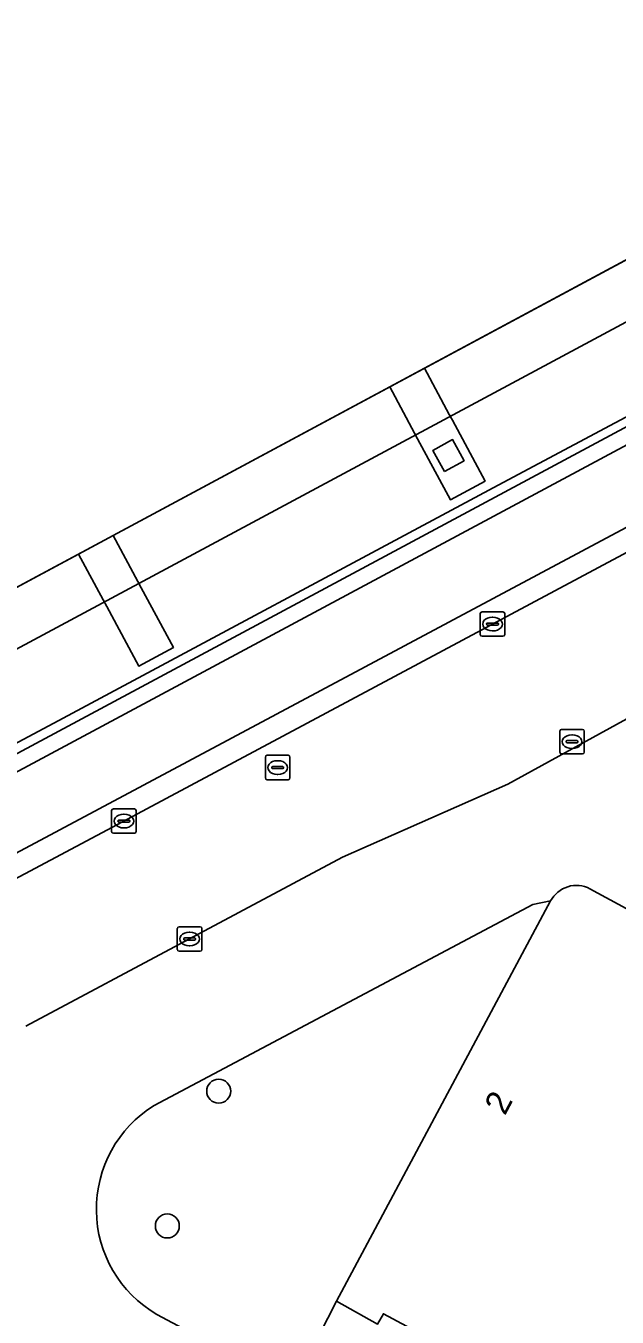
# Model space of a CAD drawing. Extents: x 159489 to 160304, y 383825 to 384531.
# Drawn here: x 159576.6 to 159600.7, y 384336.8 to 384389.5 of the extents above; entities that cross this region are included whole.
import ezdxf

# ---------------------------------------------------------------- set-up
doc = ezdxf.new("R2010")
doc.units = 0
for name, color, linetype in [('IMGEO_Berm_open', 7, 'Continuous'), ('IMGEO_Boom', 7, 'Continuous'), ('IMGEO_Dek', 7, 'Continuous'), ('IMGEO_Fietspad_gesloten', 7, 'Continuous'), ('IMGEO_Groenvoorziening', 7, 'Continuous'), ('IMGEO_Kolk', 7, 'Continuous'), ('IMGEO_Pand', 7, 'Continuous'), ('IMGEO_Pand_nummerreeks', 7, 'Continuous'), ('IMGEO_Pijler', 7, 'Continuous'), ('IMGEO_Rijbaan_lokaal_gesloten', 7, 'Continuous'), ('IMGEO_Rijbaan_regionaal_gesloten', 7, 'Continuous'), ('IMGEO_Rioolput', 7, 'Continuous'), ('IMGEO_Verkeerseiland_open', 7, 'Continuous'), ('IMGEO_Voetpad_open', 7, 'Continuous')]:
    doc.layers.add(name, color=color, linetype=linetype)

msp = doc.modelspace()

# ---------------------------------------------------------------- linework, layer by layer
at = {"layer": 'IMGEO_Berm_open'}
msp.add_lwpolyline([(159506.853, 384322.564), (159549.818, 384345.616), (159555.628, 384348.734), (159555.907, 384348.884), (159569.121, 384355.973), (159618.393, 384382.41), (159620.115, 384383.333), (159619.966, 384383.61), (159617.94, 384382.518), (159616.597, 384381.793), (159595.84, 384370.739), (159577.717, 384361.023), (159568.472, 384356.103), (159557.818, 384350.431), (159555.814, 384349.365), (159555.254, 384349.067), (159549.006, 384345.74), (159548.566, 384345.506), (159543.661, 384342.895), (159543.262, 384342.679), (159524.772, 384332.69)], dxfattribs=at)
at = {"layer": 'IMGEO_Boom'}
for centre in [(159584.446, 384346.009), (159582.351, 384340.508)]:
    msp.add_circle(centre, 0.489, dxfattribs=at)
at = {"layer": 'IMGEO_Dek'}
msp.add_lwpolyline([(159488.508, 384319.441), (159491.36, 384314.274), (159493.126, 384315.218), (159493.745, 384315.549), (159500.607, 384319.217), (159503.5, 384320.764), (159504.356, 384321.224), (159506.58, 384322.417), (159506.853, 384322.564), (159543.492, 384342.222), (159549.818, 384345.616), (159555.628, 384348.734), (159555.907, 384348.884), (159569.121, 384355.973), (159618.393, 384382.41), (159620.115, 384383.333), (159619.966, 384383.61), (159618.385, 384386.561), (159617.271, 384388.641)], close=True, dxfattribs=at)
at = {"layer": 'IMGEO_Fietspad_gesloten'}
for points in [[(159700.906, 384425.794), (159682.221, 384415.781), (159622.046, 384383.628), (159620.424, 384382.758), (159619.93, 384382.493), (159571.207, 384356.355), (159556.599, 384348.661)], [(159562.194, 384348.219), (159572.535, 384353.778), (159693.459, 384418.367)]]:
    msp.add_lwpolyline(points, dxfattribs=at)
at = {"layer": 'IMGEO_Groenvoorziening'}
for points in [[(159597.986, 384353.77), (159597.261, 384353.625), (159581.812, 384345.424)], [(159581.925, 384336.895), (159587.468, 384333.95), (159589.25, 384337.446), (159597.986, 384353.77)]]:
    msp.add_lwpolyline(points, dxfattribs=at)
msp.add_arc((159584.432, 384341.193), 4.976, 121.7686, 239.7495, dxfattribs=at)
at = {"layer": 'IMGEO_Kolk'}
for p, q in [((159595.114, 384364.644), (159595.114, 384365.496)), ((159595.189, 384365.57), (159596.041, 384365.57)), ((159595.602, 384365.35), (159595.627, 384365.35)), ((159596.115, 384365.496), (159596.115, 384364.644)), ((159595.373, 384365.064), (159595.373, 384365.076)), ((159595.811, 384365.027), (159595.413, 384365.027)), ((159595.416, 384365.113), (159595.814, 384365.113)), ((159595.625, 384364.79), (159595.6, 384364.79)), ((159595.857, 384365.076), (159595.857, 384365.064)), ((159596.041, 384364.57), (159595.189, 384364.57)), ((159598.358, 384359.845), (159598.358, 384360.697)), ((159598.433, 384360.771), (159599.285, 384360.771)), ((159598.846, 384360.551), (159598.871, 384360.551)), ((159599.359, 384360.697), (159599.359, 384359.845)), ((159598.617, 384360.265), (159598.617, 384360.277)), ((159599.055, 384360.228), (159598.657, 384360.228)), ((159598.66, 384360.314), (159599.058, 384360.314)), ((159598.869, 384359.991), (159598.844, 384359.991)), ((159599.101, 384360.277), (159599.101, 384360.265)), ((159599.285, 384359.771), (159598.433, 384359.771)), ((159580.08, 384356.605), (159580.08, 384357.457)), ((159580.155, 384357.531), (159581.007, 384357.531)), ((159580.568, 384357.311), (159580.593, 384357.311)), ((159581.081, 384357.457), (159581.081, 384356.605)), ((159580.339, 384357.025), (159580.339, 384357.037)), ((159580.777, 384356.988), (159580.379, 384356.988)), ((159580.382, 384357.074), (159580.78, 384357.074)), ((159580.823, 384357.037), (159580.823, 384357.025)), ((159581.007, 384356.531), (159580.155, 384356.531)), ((159580.591, 384356.751), (159580.566, 384356.751)), ((159582.759, 384351.794), (159582.759, 384352.646)), ((159582.834, 384352.72), (159583.686, 384352.72)), ((159583.76, 384352.646), (159583.76, 384351.794)), ((159583.018, 384352.214), (159583.018, 384352.226)), ((159583.456, 384352.177), (159583.058, 384352.177)), ((159583.061, 384352.263), (159583.459, 384352.263)), ((159583.247, 384352.5), (159583.272, 384352.5)), ((159583.502, 384352.226), (159583.502, 384352.214)), ((159583.686, 384351.72), (159582.834, 384351.72)), ((159583.27, 384351.94), (159583.245, 384351.94))]:
    msp.add_line(p, q, dxfattribs=at)
for points in [[(159595.114, 384364.644), (159595.114, 384365.496)], [(159595.189, 384365.57), (159596.041, 384365.57)], [(159596.115, 384365.496), (159596.115, 384364.644)], [(159596.041, 384364.57), (159595.189, 384364.57)], [(159598.358, 384359.845), (159598.358, 384360.697)], [(159598.433, 384360.771), (159599.285, 384360.771)], [(159599.359, 384360.697), (159599.359, 384359.845)], [(159599.285, 384359.771), (159598.433, 384359.771)], [(159580.08, 384356.605), (159580.08, 384357.457)], [(159580.155, 384357.531), (159581.007, 384357.531)], [(159581.081, 384357.457), (159581.081, 384356.605)], [(159581.007, 384356.531), (159580.155, 384356.531)], [(159582.759, 384351.794), (159582.759, 384352.646)], [(159582.834, 384352.72), (159583.686, 384352.72)], [(159583.76, 384352.646), (159583.76, 384351.794)], [(159583.686, 384351.72), (159582.834, 384351.72)]]:
    msp.add_lwpolyline(points, dxfattribs=at)
for centre, radius, start, end in [((159595.191, 384365.494), 0.0765, 91.552, 178.448), ((159595.191, 384365.494), 0.0765, 91.552, 178.448), ((159596.039, 384365.494), 0.0765, 1.552, 88.448), ((159596.039, 384365.494), 0.0765, 1.552, 88.448), ((159595.413, 384365.073), 0.0403, 85.8775, 175.7526), ((159595.41, 384365.063), 0.0366, 178.938, 274.7102), ((159595.814, 384365.07), 0.043, 264.8664, 352.4533), ((159595.818, 384365.075), 0.0386, 1.7309, 96.639), ((159595.191, 384364.646), 0.0765, 181.552, 268.448), ((159595.191, 384364.646), 0.0765, 181.552, 268.448), ((159596.039, 384364.646), 0.0765, 271.552, 358.448), ((159596.039, 384364.646), 0.0765, 271.552, 358.448), ((159598.435, 384360.695), 0.0765, 91.552, 178.448), ((159598.435, 384360.695), 0.0765, 91.552, 178.448), ((159599.283, 384360.695), 0.0765, 1.552, 88.448), ((159599.283, 384360.695), 0.0765, 1.552, 88.448), ((159598.657, 384360.274), 0.0403, 85.8775, 175.7526), ((159598.654, 384360.264), 0.0366, 178.938, 274.7102), ((159599.058, 384360.271), 0.043, 264.8664, 352.4533), ((159599.062, 384360.276), 0.0386, 1.7309, 96.639), ((159598.435, 384359.847), 0.0765, 181.552, 268.448), ((159598.435, 384359.847), 0.0765, 181.552, 268.448), ((159599.283, 384359.847), 0.0765, 271.552, 358.448), ((159599.283, 384359.847), 0.0765, 271.552, 358.448), ((159580.157, 384357.455), 0.0765, 91.552, 178.448), ((159580.157, 384357.455), 0.0765, 91.552, 178.448), ((159581.005, 384357.455), 0.0765, 1.552, 88.448), ((159581.005, 384357.455), 0.0765, 1.552, 88.448), ((159580.379, 384357.034), 0.0403, 85.8775, 175.7526), ((159580.376, 384357.024), 0.0366, 178.938, 274.7102), ((159580.78, 384357.031), 0.043, 264.8664, 352.4533), ((159580.784, 384357.036), 0.0386, 1.7309, 96.639), ((159580.157, 384356.607), 0.0765, 181.552, 268.448), ((159580.157, 384356.607), 0.0765, 181.552, 268.448), ((159581.005, 384356.607), 0.0765, 271.552, 358.448), ((159581.005, 384356.607), 0.0765, 271.552, 358.448), ((159582.836, 384352.644), 0.0765, 91.552, 178.448), ((159582.836, 384352.644), 0.0765, 91.552, 178.448), ((159583.684, 384352.644), 0.0765, 1.552, 88.448), ((159583.684, 384352.644), 0.0765, 1.552, 88.448), ((159583.058, 384352.223), 0.0403, 85.8775, 175.7526), ((159583.055, 384352.213), 0.0366, 178.938, 274.7102), ((159583.459, 384352.22), 0.043, 264.8664, 352.4533), ((159583.463, 384352.225), 0.0386, 1.7309, 96.639), ((159582.836, 384351.796), 0.0765, 181.552, 268.448), ((159582.836, 384351.796), 0.0765, 181.552, 268.448), ((159583.684, 384351.796), 0.0765, 271.552, 358.448), ((159583.684, 384351.796), 0.0765, 271.552, 358.448)]:
    msp.add_arc(centre, radius, start, end, dxfattribs=at)
for centre, major_axis, ratio, start_param, end_param in [((159595.601, 384365.07), (-0.387, 0.002), 0.722429, 4.712389, 7.853982), ((159595.626, 384365.07), (-0.39, 0.002), 0.717154, 1.570796, 4.712389), ((159598.845, 384360.271), (-0.387, 0.002), 0.722429, 4.712389, 7.853982), ((159598.87, 384360.271), (-0.39, 0.002), 0.717154, 1.570796, 4.712389), ((159580.567, 384357.031), (-0.387, 0.002), 0.722429, 4.712389, 7.853982), ((159580.592, 384357.031), (-0.39, 0.002), 0.717154, 1.570796, 4.712389), ((159583.246, 384352.22), (-0.387, 0.002), 0.722429, 4.712389, 7.853982), ((159583.271, 384352.22), (-0.39, 0.002), 0.717154, 1.570796, 4.712389)]:
    msp.add_ellipse(centre, major_axis=major_axis, ratio=ratio, start_param=start_param, end_param=end_param, dxfattribs=at)
at = {"layer": 'IMGEO_Pand'}
for points in [[(159682.896, 384327.942), (159623.816, 384359.804), (159624.059, 384360.245), (159623.309, 384360.657), (159623.062, 384360.208), (159618.493, 384362.659), (159618.727, 384363.096), (159617.547, 384363.691), (159617.084, 384363.924), (159612.282, 384355.014), (159609.456, 384356.538), (159609.794, 384357.17), (159609.409, 384357.376), (159608.96, 384356.518), (159606.901, 384357.605), (159605.205, 384354.438), (159602.39, 384355.944), (159601.071, 384353.466), (159599.589, 384354.271)], [(159597.986, 384353.77), (159589.25, 384337.446), (159590.921, 384336.498), (159591.162, 384336.929), (159595.684, 384334.503)]]:
    msp.add_lwpolyline(points, dxfattribs=at)
msp.add_arc((159599.038, 384353.22), 1.187, 62.3087, 152.4035, dxfattribs=at)
at = {"layer": 'IMGEO_Pijler'}
for points in [[(159592.84, 384375.511), (159591.422, 384374.749), (159592.433, 384372.865), (159592.56, 384372.628), (159593.894, 384370.142), (159595.312, 384370.903), (159593.976, 384373.392), (159593.851, 384373.625)], [(159593.661, 384371.296), (159594.458, 384371.735), (159593.983, 384372.597), (159593.186, 384372.158)], [(159593.661, 384371.296), (159593.186, 384372.158), (159593.983, 384372.597), (159594.458, 384371.735)], [(159580.139, 384368.685), (159578.728, 384367.927), (159579.736, 384366.053), (159579.879, 384365.787), (159581.186, 384363.356), (159582.596, 384364.114), (159581.288, 384366.547), (159581.147, 384366.81)]]:
    msp.add_lwpolyline(points, close=True, dxfattribs=at)
at = {"layer": 'IMGEO_Rijbaan_lokaal_gesloten'}
for points in [[(159696.183, 384418.774), (159693.863, 384417.603), (159580.529, 384357.003), (159566.867, 384349.736)], [(159576.58, 384348.662), (159583.26, 384352.22), (159589.5, 384355.56), (159596.233, 384358.541), (159604.138, 384362.877), (159611.421, 384366.774), (159627.528, 384375.393), (159633.379, 384378.441), (159633.124, 384378.917), (159634.128, 384379.44)]]:
    msp.add_lwpolyline(points, dxfattribs=at)
at = {"layer": 'IMGEO_Rijbaan_regionaal_gesloten'}
msp.add_lwpolyline([(159489.531, 384317.589), (159499.262, 384322.788), (159516.94, 384332.242), (159553.091, 384351.689), (159570.032, 384360.747), (159613.14, 384383.883), (159618.33, 384386.664), (159617.271, 384388.641), (159488.508, 384319.441)], close=True, dxfattribs=at)
msp.add_lwpolyline([(159524.772, 384332.69), (159543.262, 384342.679), (159543.661, 384342.895), (159548.566, 384345.506), (159549.006, 384345.74), (159555.254, 384349.067), (159555.814, 384349.365), (159557.818, 384350.431), (159568.472, 384356.103), (159577.717, 384361.023), (159595.84, 384370.739), (159616.597, 384381.793), (159617.94, 384382.518), (159619.966, 384383.61), (159618.33, 384386.664), (159613.14, 384383.883), (159570.032, 384360.747), (159553.091, 384351.689), (159516.94, 384332.242)], dxfattribs=at)
at = {"layer": 'IMGEO_Rioolput'}
for p, q in [((159586.352, 384358.789), (159586.352, 384359.641)), ((159586.427, 384359.715), (159587.279, 384359.715)), ((159586.84, 384359.495), (159586.865, 384359.495)), ((159587.353, 384359.641), (159587.353, 384358.789)), ((159586.611, 384359.209), (159586.611, 384359.221)), ((159587.049, 384359.172), (159586.651, 384359.172)), ((159586.654, 384359.258), (159587.052, 384359.258)), ((159586.863, 384358.935), (159586.838, 384358.935)), ((159587.095, 384359.221), (159587.095, 384359.209)), ((159587.279, 384358.715), (159586.427, 384358.715))]:
    msp.add_line(p, q, dxfattribs=at)
for points in [[(159586.352, 384358.789), (159586.352, 384359.641)], [(159586.427, 384359.715), (159587.279, 384359.715)], [(159587.353, 384359.641), (159587.353, 384358.789)], [(159587.279, 384358.715), (159586.427, 384358.715)]]:
    msp.add_lwpolyline(points, dxfattribs=at)
for centre, radius, start, end in [((159586.429, 384359.639), 0.0765, 91.552, 178.448), ((159586.429, 384359.639), 0.0765, 91.552, 178.448), ((159587.277, 384359.639), 0.0765, 1.552, 88.448), ((159587.277, 384359.639), 0.0765, 1.552, 88.448), ((159586.651, 384359.218), 0.0403, 85.8775, 175.7526), ((159586.648, 384359.208), 0.0366, 178.938, 274.7102), ((159587.052, 384359.215), 0.043, 264.8664, 352.4533), ((159587.056, 384359.22), 0.0386, 1.7309, 96.639), ((159586.429, 384358.791), 0.0765, 181.552, 268.448), ((159586.429, 384358.791), 0.0765, 181.552, 268.448), ((159587.277, 384358.791), 0.0765, 271.552, 358.448), ((159587.277, 384358.791), 0.0765, 271.552, 358.448)]:
    msp.add_arc(centre, radius, start, end, dxfattribs=at)
for centre, major_axis, ratio, start_param, end_param in [((159586.839, 384359.215), (-0.387, 0.002), 0.722429, 4.712389, 7.853982), ((159586.864, 384359.215), (-0.39, 0.002), 0.717154, 1.570796, 4.712389)]:
    msp.add_ellipse(centre, major_axis=major_axis, ratio=ratio, start_param=start_param, end_param=end_param, dxfattribs=at)
at = {"layer": 'IMGEO_Verkeerseiland_open'}
for points in [[(159693.863, 384417.603), (159693.459, 384418.367), (159572.535, 384353.778), (159562.194, 384348.219)], [(159566.867, 384349.736), (159580.529, 384357.003), (159693.863, 384417.603)]]:
    msp.add_lwpolyline(points, dxfattribs=at)
at = {"layer": 'IMGEO_Voetpad_open'}
for points in [[(159555.907, 384348.884), (159556.599, 384348.661), (159571.207, 384356.355), (159619.93, 384382.493)], [(159604.103, 384381.564), (159592.84, 384375.511), (159593.851, 384373.625), (159593.976, 384373.392), (159595.312, 384370.903), (159593.894, 384370.142), (159592.56, 384372.628), (159592.433, 384372.865), (159591.422, 384374.749), (159580.139, 384368.685), (159581.147, 384366.81), (159581.288, 384366.547), (159582.596, 384364.114), (159581.186, 384363.356), (159579.879, 384365.787), (159579.736, 384366.053), (159578.728, 384367.927), (159567.46, 384361.871)], [(159599.589, 384354.271), (159601.071, 384353.466), (159602.39, 384355.944), (159605.205, 384354.438), (159606.901, 384357.605), (159608.96, 384356.518), (159609.409, 384357.376), (159609.794, 384357.17), (159609.456, 384356.538), (159612.282, 384355.014), (159617.084, 384363.924), (159611.421, 384366.774), (159604.138, 384362.877), (159596.233, 384358.541), (159589.5, 384355.56), (159583.26, 384352.22), (159576.58, 384348.662)], [(159581.812, 384345.424), (159597.261, 384353.625)], [(159597.261, 384353.625), (159597.986, 384353.77)], [(159595.684, 384334.503), (159591.162, 384336.929), (159590.921, 384336.498), (159589.25, 384337.446), (159587.468, 384333.95), (159581.925, 384336.895)]]:
    msp.add_lwpolyline(points, dxfattribs=at)
for centre, radius, start, end in [((159599.038, 384353.22), 1.187, 62.3087, 152.4035), ((159584.432, 384341.193), 4.976, 121.7686, 239.7495)]:
    msp.add_arc(centre, radius, start, end, dxfattribs=at)

# ---------------------------------------------------------------- texts
at = {"layer": 'IMGEO_Pand_nummerreeks'}
msp.add_text('2', height=1, rotation=61.846, dxfattribs=at).set_placement((159596.12, 384344.984))

doc.saveas('drawing.dxf')
